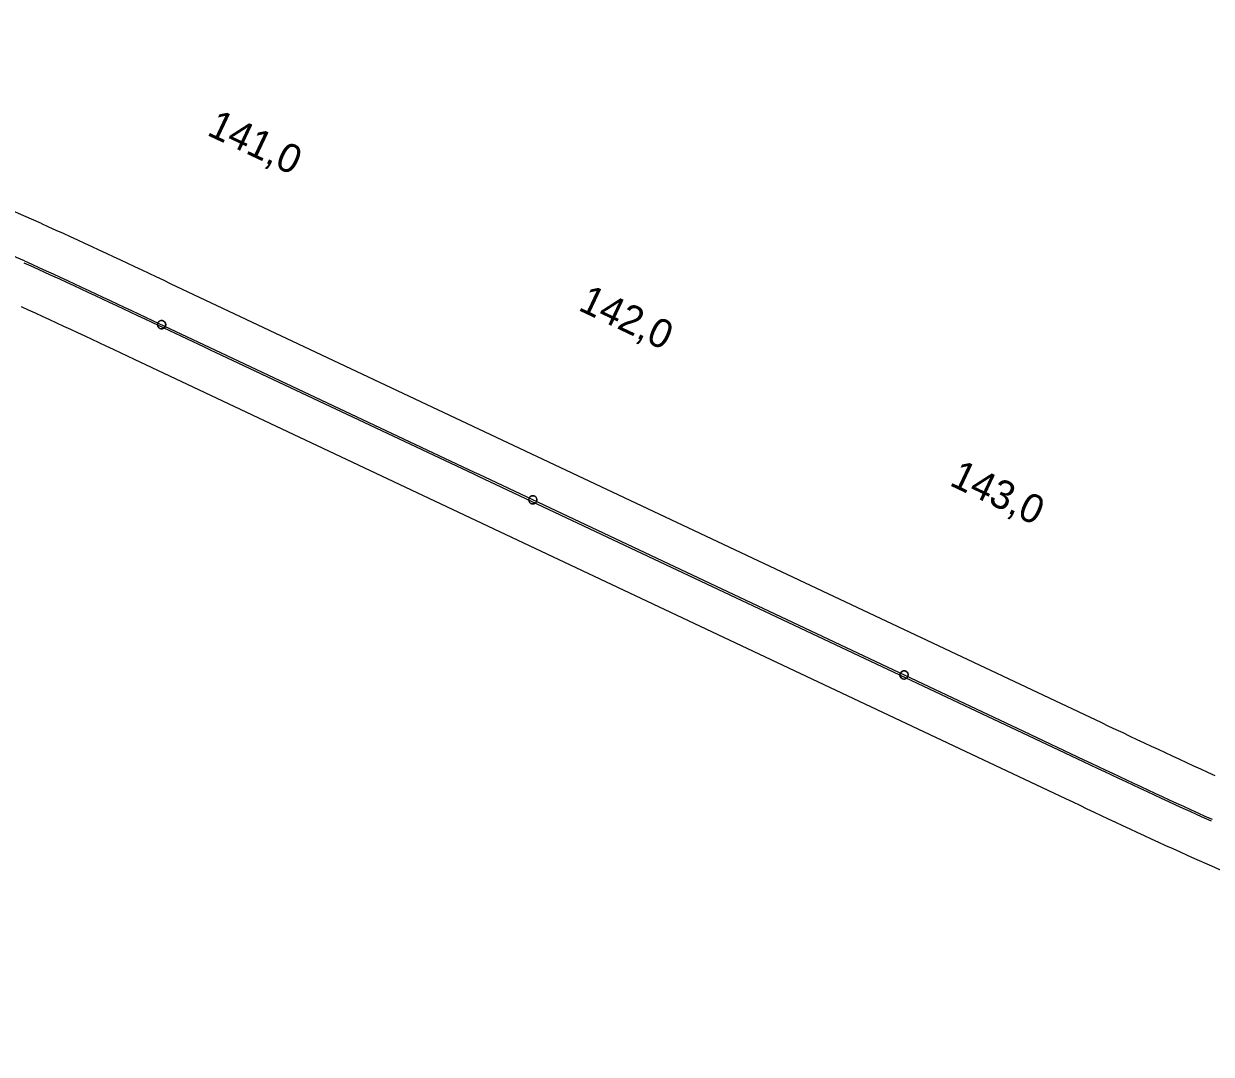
# Model space of a CAD drawing. Extents: x -670810 to -649614, y -1131928 to -1115069.
# Drawn here: x -657961 to -655068, y -1131159 to -1128648 of the extents above; entities that cross this region are included whole.
import ezdxf

# ---------------------------------------------------------------- set-up
doc = ezdxf.new("R2010")
doc.units = 0
for name, color, linetype in [('hranice_VRT_ZUR_Vysocina', 7, 'Continuous'), ('Situace - Osa koleje 2D', 7, 'Continuous'), ('Situace - Osa koleje tunel 2D', 7, 'Continuous'), ('Staničení - hlavní staničení + kolečka 1k', 7, 'Continuous')]:
    doc.layers.add(name, color=color, linetype=linetype)

# ---------------------------------------------------------------- blocks, each defined once
blk = doc.blocks.new('Sit10Kruh_118')
at = {"layer": 'Staničení - hlavní staničení + kolečka 1k'}
blk.add_lwpolyline([(10, 0), (10, 0.6), (9.9, 1.3), (9.8, 1.9), (9.7, 2.5), (9.5, 3.1), (9.3, 3.7), (9, 4.3), (8.8, 4.8), (8.4, 5.4), (8.1, 5.9), (7.7, 6.4), (7.3, 6.8), (6.8, 7.3), (6.4, 7.7), (5.9, 8.1), (5.4, 8.4), (4.8, 8.8), (4.3, 9), (3.7, 9.3), (3.1, 9.5), (2.5, 9.7), (1.9, 9.8), (1.3, 9.9), (0.6, 10), (0, 10), (-0.6, 10), (-1.3, 9.9), (-1.9, 9.8), (-2.5, 9.7), (-3.1, 9.5), (-3.7, 9.3), (-4.3, 9), (-4.8, 8.8), (-5.4, 8.4), (-5.9, 8.1), (-6.4, 7.7), (-6.8, 7.3), (-7.3, 6.8), (-7.7, 6.4), (-8.1, 5.9), (-8.4, 5.4), (-8.8, 4.8), (-9, 4.3), (-9.3, 3.7), (-9.5, 3.1), (-9.7, 2.5), (-9.8, 1.9), (-9.9, 1.3), (-10, 0.6), (-10, 0), (-10, -0.6), (-9.9, -1.3), (-9.8, -1.9), (-9.7, -2.5), (-9.5, -3.1), (-9.3, -3.7), (-9, -4.3), (-8.8, -4.8), (-8.4, -5.4), (-8.1, -5.9), (-7.7, -6.4), (-7.3, -6.8), (-6.8, -7.3), (-6.4, -7.7), (-5.9, -8.1), (-5.4, -8.4), (-4.8, -8.8), (-4.3, -9), (-3.7, -9.3), (-3.1, -9.5), (-2.5, -9.7), (-1.9, -9.8), (-1.3, -9.9), (-0.6, -10), (0, -10), (0.6, -10), (1.3, -9.9), (1.9, -9.8), (2.5, -9.7), (3.1, -9.5), (3.7, -9.3), (4.3, -9), (4.8, -8.8), (5.4, -8.4), (5.9, -8.1), (6.4, -7.7), (6.8, -7.3), (7.3, -6.8), (7.7, -6.4), (8.1, -5.9), (8.4, -5.4), (8.8, -4.8), (9, -4.3), (9.3, -3.7), (9.5, -3.1), (9.7, -2.5), (9.8, -1.9), (9.9, -1.3)], close=True, dxfattribs=at)
blk.add_circle((0, 0), 10, dxfattribs=at)
blk = doc.blocks.new('Sit10Kruh_119')
at = {"layer": 'Staničení - hlavní staničení + kolečka 1k'}
blk.add_lwpolyline([(10, 0), (9.98026, 0.6279), (9.92114, 1.25334), (9.82288, 1.87382), (9.68584, 2.4869), (9.51056, 3.09016), (9.29776, 3.68124), (9.04828, 4.2578), (8.76306, 4.81754), (8.44328, 5.35826), (8.09016, 5.87786), (7.70514, 6.37424), (7.28968, 6.84548), (6.84548, 7.28968), (6.37424, 7.70514), (5.87786, 8.09016), (5.35826, 8.44328), (4.81754, 8.76306), (4.2578, 9.04828), (3.68124, 9.29776), (3.09016, 9.51056), (2.4869, 9.68584), (1.87382, 9.82288), (1.25334, 9.92114), (0.6279, 9.98026), (0, 10), (-0.6279, 9.98026), (-1.25334, 9.92114), (-1.87382, 9.82288), (-2.4869, 9.68584), (-3.09016, 9.51056), (-3.68124, 9.29776), (-4.2578, 9.04828), (-4.81754, 8.76306), (-5.35826, 8.44328), (-5.87786, 8.09016), (-6.37424, 7.70514), (-6.84548, 7.28968), (-7.28968, 6.84548), (-7.70514, 6.37424), (-8.09016, 5.87786), (-8.44328, 5.35826), (-8.76306, 4.81754), (-9.04828, 4.2578), (-9.29776, 3.68124), (-9.51056, 3.09016), (-9.68584, 2.4869), (-9.82288, 1.87382), (-9.92114, 1.25334), (-9.98026, 0.6279), (-10, 0), (-9.98026, -0.6279), (-9.92114, -1.25334), (-9.82288, -1.87382), (-9.68584, -2.4869), (-9.51056, -3.09016), (-9.29776, -3.68124), (-9.04828, -4.2578), (-8.76306, -4.81754), (-8.44328, -5.35826), (-8.09016, -5.87786), (-7.70514, -6.37424), (-7.28968, -6.84548), (-6.84548, -7.28968), (-6.37424, -7.70514), (-5.87786, -8.09016), (-5.35826, -8.44328), (-4.81754, -8.76306), (-4.2578, -9.04828), (-3.68124, -9.29776), (-3.09016, -9.51056), (-2.4869, -9.68584), (-1.87382, -9.82288), (-1.25334, -9.92114), (-0.6279, -9.98026), (0, -10), (0.6279, -9.98026), (1.25334, -9.92114), (1.87382, -9.82288), (2.4869, -9.68584), (3.09016, -9.51056), (3.68124, -9.29776), (4.2578, -9.04828), (4.81754, -8.76306), (5.35826, -8.44328), (5.87786, -8.09016), (6.37424, -7.70514), (6.84548, -7.28968), (7.28968, -6.84548), (7.70514, -6.37424), (8.09016, -5.87786), (8.44328, -5.35826), (8.76306, -4.81754), (9.04828, -4.2578), (9.29776, -3.68124), (9.51056, -3.09016), (9.68584, -2.4869), (9.82288, -1.87382), (9.92114, -1.25334)], close=True, dxfattribs=at)
blk.add_circle((0, 0), 10, dxfattribs=at)
blk = doc.blocks.new('Sit10Kruh_120')
at = {"layer": 'Staničení - hlavní staničení + kolečka 1k'}
blk.add_lwpolyline([(10, 0), (9.98026, 0.6279), (9.92114, 1.25334), (9.82288, 1.87382), (9.68584, 2.4869), (9.51056, 3.09016), (9.29776, 3.68124), (9.04828, 4.2578), (8.76306, 4.81754), (8.44328, 5.35826), (8.09016, 5.87786), (7.70514, 6.37424), (7.28968, 6.84548), (6.84548, 7.28968), (6.37424, 7.70514), (5.87786, 8.09016), (5.35826, 8.44328), (4.81754, 8.76306), (4.2578, 9.04828), (3.68124, 9.29776), (3.09016, 9.51056), (2.4869, 9.68584), (1.87382, 9.82288), (1.25334, 9.92114), (0.6279, 9.98026), (0, 10), (-0.6279, 9.98026), (-1.25334, 9.92114), (-1.87382, 9.82288), (-2.4869, 9.68584), (-3.09016, 9.51056), (-3.68124, 9.29776), (-4.2578, 9.04828), (-4.81754, 8.76306), (-5.35826, 8.44328), (-5.87786, 8.09016), (-6.37424, 7.70514), (-6.84548, 7.28968), (-7.28968, 6.84548), (-7.70514, 6.37424), (-8.09016, 5.87786), (-8.44328, 5.35826), (-8.76306, 4.81754), (-9.04828, 4.2578), (-9.29776, 3.68124), (-9.51056, 3.09016), (-9.68584, 2.4869), (-9.82288, 1.87382), (-9.92114, 1.25334), (-9.98026, 0.6279), (-10, 0), (-9.98026, -0.6279), (-9.92114, -1.25334), (-9.82288, -1.87382), (-9.68584, -2.4869), (-9.51056, -3.09016), (-9.29776, -3.68124), (-9.04828, -4.2578), (-8.76306, -4.81754), (-8.44328, -5.35826), (-8.09016, -5.87786), (-7.70514, -6.37424), (-7.28968, -6.84548), (-6.84548, -7.28968), (-6.37424, -7.70514), (-5.87786, -8.09016), (-5.35826, -8.44328), (-4.81754, -8.76306), (-4.2578, -9.04828), (-3.68124, -9.29776), (-3.09016, -9.51056), (-2.4869, -9.68584), (-1.87382, -9.82288), (-1.25334, -9.92114), (-0.6279, -9.98026), (0, -10), (0.6279, -9.98026), (1.25334, -9.92114), (1.87382, -9.82288), (2.4869, -9.68584), (3.09016, -9.51056), (3.68124, -9.29776), (4.2578, -9.04828), (4.81754, -8.76306), (5.35826, -8.44328), (5.87786, -8.09016), (6.37424, -7.70514), (6.84548, -7.28968), (7.28968, -6.84548), (7.70514, -6.37424), (8.09016, -5.87786), (8.44328, -5.35826), (8.76306, -4.81754), (9.04828, -4.2578), (9.29776, -3.68124), (9.51056, -3.09016), (9.68584, -2.4869), (9.82288, -1.87382), (9.92114, -1.25334)], close=True, dxfattribs=at)
blk.add_circle((0, 0), 10, dxfattribs=at)

msp = doc.modelspace()

# ---------------------------------------------------------------- linework, layer by layer
at = {"layer": 'hranice_VRT_ZUR_Vysocina'}
for points in [[(-657918.4, -1129135.1), (-657918.3, -1129135.2), (-657900.8, -1129143), (-657883.2, -1129151), (-657865.6, -1129159), (-657848, -1129167), (-657830.4, -1129175), (-657812.9, -1129183.1), (-657795.4, -1129191.2), (-657778, -1129199.3), (-657760.5, -1129207.5), (-657743.1, -1129215.6), (-657725.8, -1129223.8), (-657708.4, -1129231.9), (-657691.1, -1129240.1), (-657673.7, -1129248.2), (-657656.4, -1129256.4), (-657639.1, -1129264.6), (-657621.8, -1129272.7), (-657604.5, -1129280.9), (-655335.8, -1130351.2), (-655318.6, -1130359.4), (-655301.3, -1130367.5), (-655284, -1130375.6), (-655266.7, -1130383.8), (-655249.5, -1130391.9), (-655232.2, -1130400), (-655215, -1130408.1), (-655197.8, -1130416.2), (-655180.6, -1130424.3), (-655163.3, -1130432.3), (-655146.1, -1130440.3), (-655128.9, -1130448.3), (-655111.7, -1130456.2), (-655094.5, -1130464.1), (-655077.3, -1130471.9), (-655060.1, -1130479.8)], [(-657967.6, -1129337.4), (-657950.4, -1129345.3), (-657933.2, -1129353.1), (-657916, -1129361), (-657898.8, -1129368.9), (-657881.6, -1129376.9), (-657864.4, -1129384.9), (-657847.2, -1129392.9), (-657830, -1129401), (-657812.8, -1129409.1), (-657795.5, -1129417.2), (-657778.3, -1129425.3), (-657761, -1129433.4), (-657743.8, -1129441.5), (-657726.5, -1129449.7), (-657709.2, -1129457.8), (-657691.9, -1129466), (-655423.2, -1130536.3), (-655405.9, -1130544.5), (-655388.6, -1130552.6), (-655371.3, -1130560.8), (-655354, -1130568.9), (-655336.7, -1130577.1), (-655319.4, -1130585.3), (-655302, -1130593.4), (-655284.6, -1130601.6), (-655267.2, -1130609.7), (-655249.8, -1130617.9), (-655232.3, -1130626), (-655214.8, -1130634.1), (-655197.3, -1130642.1), (-655179.8, -1130650.2), (-655162.2, -1130658.2), (-655144.6, -1130666.2), (-655127, -1130674.2), (-655109.4, -1130682), (-655109.3, -1130682.1)]]:
    msp.add_lwpolyline(points, dxfattribs=at)
for centre, start, end in [((-661474.3, -1137080.3), 65.88874, 75.6195), ((-651553.4, -1122736.9), 245.88876, 255.36511)]:
    msp.add_arc(centre, 8704.6, start, end, dxfattribs=at)
at = {"layer": 'Situace - Osa koleje 2D'}
for p, q in [((-657649.2, -1129375.6), (-657521.8, -1129435.7)), ((-657647.2, -1129371.3), (-657522.1, -1129430.4)), ((-657509.3, -1129436.4), (-656864.3, -1129740.7)), ((-657509, -1129441.7), (-656865.7, -1129745.2)), ((-656854.3, -1129750.6), (-655528, -1130376.3)), ((-656852.9, -1129746.1), (-655526, -1130372.1))]:
    msp.add_line(p, q, dxfattribs=at)
for points in [[(-657961.2, -1129230.7), (-657943.8, -1129238.5), (-657926.4, -1129246.3), (-657909, -1129254.2), (-657891.6, -1129262.2), (-657874.2, -1129270.2), (-657856.9, -1129278.2), (-657839.5, -1129286.2), (-657822.2, -1129294.2), (-657804.9, -1129302.3), (-657787.6, -1129310.4), (-657770.3, -1129318.5), (-657753, -1129326.7), (-657735.7, -1129334.8), (-657718.4, -1129342.9), (-657701.1, -1129351.1), (-657683.8, -1129359.2), (-657666.5, -1129367.4), (-657649.2, -1129375.6)], [(-657959.3, -1129226.4), (-657941.8, -1129234.2), (-657924.4, -1129242.1), (-657907, -1129250), (-657889.6, -1129257.9), (-657872.2, -1129265.9), (-657854.9, -1129273.9), (-657837.5, -1129281.9), (-657820.2, -1129290), (-657802.9, -1129298.1), (-657785.6, -1129306.2), (-657768.3, -1129314.3), (-657751, -1129322.4), (-657733.7, -1129330.6), (-657716.4, -1129338.7), (-657699.1, -1129346.9), (-657681.8, -1129355), (-657664.5, -1129363.2), (-657647.2, -1129371.3)]]:
    msp.add_lwpolyline(points, dxfattribs=at)
msp.add_arc((-661474.4, -1137080.4), 8604.7, 65.88879, 70.43633, dxfattribs=at)
at = {"layer": 'Situace - Osa koleje tunel 2D'}
for p, q in [((-657522.1, -1129430.4), (-657509.3, -1129436.4)), ((-657521.8, -1129435.7), (-657509, -1129441.7)), ((-656865.7, -1129745.2), (-656854.3, -1129750.6)), ((-656864.3, -1129740.7), (-656852.9, -1129746.1)), ((-655528, -1130376.3), (-655380.6, -1130445.9)), ((-655526, -1130372.1), (-655378.5, -1130441.6))]:
    msp.add_line(p, q, dxfattribs=at)
for points in [[(-655380.6, -1130445.9), (-655363.3, -1130454), (-655346, -1130462.2), (-655328.7, -1130470.3), (-655311.4, -1130478.5), (-655294.1, -1130486.6), (-655276.8, -1130494.8), (-655259.5, -1130502.9), (-655242.2, -1130511), (-655224.9, -1130519.1), (-655207.6, -1130527.2), (-655190.2, -1130535.3), (-655172.9, -1130543.3), (-655155.5, -1130551.3), (-655138.1, -1130559.3), (-655120.8, -1130567.2), (-655103.4, -1130575.1), (-655085.9, -1130583), (-655068.5, -1130590.8)], [(-655378.5, -1130441.6), (-655361.2, -1130449.8), (-655343.9, -1130457.9), (-655326.7, -1130466.1), (-655309.4, -1130474.2), (-655292.1, -1130482.4), (-655274.8, -1130490.5), (-655257.5, -1130498.7), (-655240.2, -1130506.8), (-655222.9, -1130514.9), (-655205.6, -1130522.9), (-655188.2, -1130531), (-655170.9, -1130539), (-655153.5, -1130547), (-655136.2, -1130555), (-655118.8, -1130562.9), (-655101.4, -1130570.9), (-655084, -1130578.7), (-655066.5, -1130586.5)]]:
    msp.add_lwpolyline(points, dxfattribs=at)

# ---------------------------------------------------------------- block references
at = {"layer": 'Staničení - hlavní staničení + kolečka 1k', "rotation": -25.256812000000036}
for name, p in [('Sit10Kruh_118', (-657625.5, -1129381.6)), ('Sit10Kruh_119', (-656721.1, -1129808.3)), ('Sit10Kruh_120', (-655816.7, -1130234.9))]:
    msp.add_blockref(name, p, dxfattribs=at)

# ---------------------------------------------------------------- texts
at = {"layer": 'Staničení - hlavní staničení + kolečka 1k'}
for s, p in [('141,0', (-657517.7, -1128918.3)), ('142,0', (-656613.3, -1129344.9)), ('143,0', (-655708.9, -1129771.6))]:
    msp.add_text(s, height=70, rotation=334.7432, dxfattribs=at).set_placement(p)

doc.saveas('drawing.dxf')
